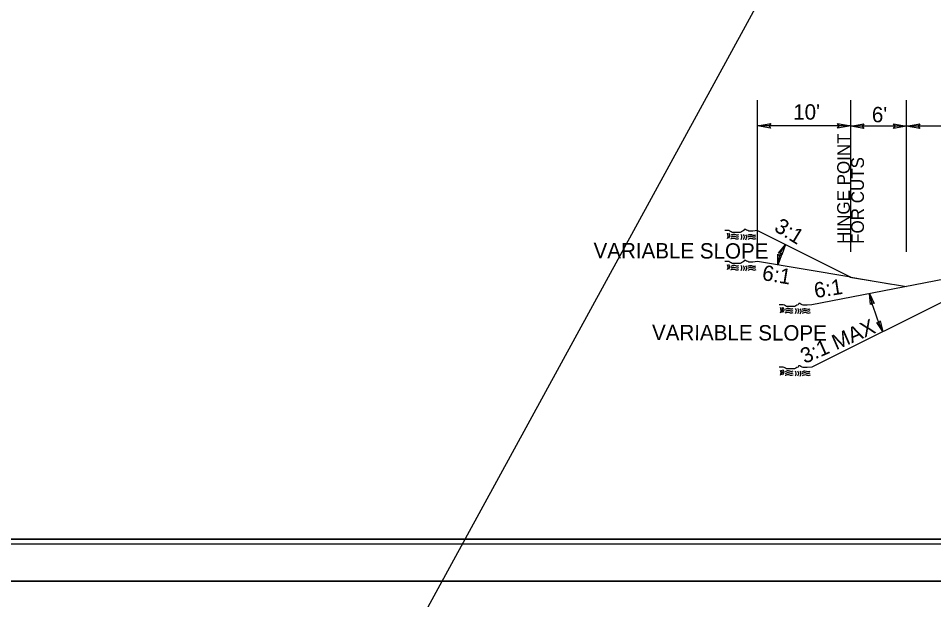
# Model space of a CAD drawing. Extents: x 2241081 to 2251104, y 658534 to 663427.
# Drawn here: x 2245690 to 2246181.2, y 660714.3 to 661026.5 of the extents above; entities that cross this region are included whole.
import ezdxf

# ---------------------------------------------------------------- set-up
doc = ezdxf.new("R2010")
doc.units = 0
for name, color, linetype in [('Old_Level_1', 7, 'Continuous'), ('Old_Level_2', 7, 'Continuous'), ('Prop Dimension', 7, 'Continuous'), ('Prop Dimension Text', 7, 'Continuous'), ('Prop PHM Text', 7, 'Continuous'), ('Sheet Cutting Line CELL', 7, 'Continuous'), ('Sheet Plan CELL', 7, 'Continuous'), ('Sheet Plot Border Inside CELL', 7, 'Continuous'), ('Sheet Plot Border Outside CELL', 7, 'Continuous'), ('Typical Hinge Slope Interstate CELL', 7, 'Continuous'), ('Typical Terminator CELL', 7, 'Continuous')]:
    doc.layers.add(name, color=color, linetype=linetype)

msp = doc.modelspace()

# ---------------------------------------------------------------- linework, layer by layer
at = {"layer": 'Old_Level_1'}
for p, q in [((2246086.68, 660912.48), (2246136.68, 660887.48)), ((2246136.68, 660887.48), (2246086.68, 660895.82)), ((2246224.69, 660893.65), (2246115.86, 660872.7)), ((2246136.68, 660887.48), (2246158.68, 660883.81))]:
    msp.add_line(p, q, dxfattribs=at)
for points in [[(2246086.68, 660912.48), (2246084.21, 660912.17), (2246083.6, 660912.17), (2246082.67, 660912.17), (2246082.06, 660912.17), (2246081.44, 660912.48), (2246080.82, 660912.79), (2246080.21, 660913.1), (2246079.59, 660913.1), (2246079.28, 660912.48), (2246078.67, 660912.17), (2246078.05, 660911.87), (2246077.43, 660911.56), (2246076.82, 660911.56), (2246076.2, 660911.56), (2246075.59, 660911.56), (2246074.97, 660911.56), (2246074.35, 660911.56), (2246073.74, 660911.56), (2246073.12, 660911.56), (2246072.5, 660911.87), (2246071.89, 660912.17), (2246071.27, 660912.48), (2246070.35, 660912.48), (2246069.73, 660912.48), (2246069.11, 660912.48)], [(2246086.68, 660895.82), (2246084.21, 660895.51), (2246083.6, 660895.51), (2246082.67, 660895.51), (2246082.06, 660895.51), (2246081.44, 660895.82), (2246080.82, 660896.13), (2246080.21, 660896.44), (2246079.59, 660896.43), (2246079.28, 660895.82), (2246078.67, 660895.51), (2246078.05, 660895.2), (2246077.43, 660894.89), (2246076.82, 660894.89), (2246076.2, 660894.89), (2246075.59, 660894.89), (2246074.97, 660894.89), (2246074.35, 660894.89), (2246073.74, 660894.89), (2246073.12, 660894.89), (2246072.5, 660895.2), (2246071.89, 660895.51), (2246071.27, 660895.82), (2246070.35, 660895.82), (2246069.73, 660895.82), (2246069.11, 660895.82)], [(2246115.86, 660872.7), (2246113.39, 660872.39), (2246112.78, 660872.39), (2246111.85, 660872.39), (2246111.23, 660872.39), (2246110.62, 660872.7), (2246110, 660873.01), (2246109.39, 660873.32), (2246108.77, 660873.32), (2246108.46, 660872.7), (2246107.84, 660872.39), (2246107.23, 660872.08), (2246106.61, 660871.78), (2246106, 660871.78), (2246105.38, 660871.78), (2246104.76, 660871.78), (2246104.15, 660871.78), (2246103.53, 660871.78), (2246102.92, 660871.78), (2246102.3, 660871.78), (2246101.68, 660872.08), (2246101.07, 660872.39), (2246100.45, 660872.7), (2246099.53, 660872.7), (2246098.91, 660872.7), (2246098.29, 660872.7)], [(2246115.82, 660839.21), (2246113.35, 660838.9), (2246112.74, 660838.9), (2246111.81, 660838.9), (2246111.19, 660838.9), (2246110.58, 660839.21), (2246109.96, 660839.52), (2246109.35, 660839.83), (2246108.73, 660839.83), (2246108.42, 660839.21), (2246107.8, 660838.9), (2246107.19, 660838.59), (2246106.57, 660838.29), (2246105.96, 660838.29), (2246105.34, 660838.29), (2246104.72, 660838.29), (2246104.11, 660838.29), (2246103.49, 660838.29), (2246102.87, 660838.29), (2246102.26, 660838.29), (2246101.64, 660838.59), (2246101.03, 660838.9), (2246100.41, 660839.21), (2246099.48, 660839.21), (2246098.87, 660839.21), (2246098.25, 660839.21)]]:
    msp.add_lwpolyline(points, dxfattribs=at)
for points in [[(2246070.37, 660911.04), (2246070.79, 660909.79), (2246070.33, 660908.14)], [(2246070.37, 660911.04), (2246070.79, 660909.79), (2246070.33, 660908.14)], [(2246071.15, 660911.12), (2246071.57, 660909.87), (2246071.12, 660908.23)], [(2246071.15, 660911.12), (2246071.57, 660909.87), (2246071.12, 660908.23)], [(2246072.35, 660908.05), (2246073.86, 660908.47), (2246075.45, 660908.07), (2246076.6, 660908.33)], [(2246072.35, 660908.05), (2246073.86, 660908.47), (2246075.45, 660908.07), (2246076.6, 660908.33)], [(2246072.47, 660909.1), (2246073.98, 660909.53), (2246075.56, 660909.12), (2246076.7, 660909.38)], [(2246072.47, 660909.1), (2246073.98, 660909.53), (2246075.56, 660909.12), (2246076.7, 660909.38)], [(2246072.48, 660910.15), (2246073.98, 660910.58), (2246075.57, 660910.18), (2246076.71, 660910.43)], [(2246072.48, 660910.15), (2246073.98, 660910.58), (2246075.57, 660910.18), (2246076.71, 660910.43)], [(2246077.74, 660910.5), (2246078.15, 660909.26), (2246077.71, 660907.62)], [(2246077.74, 660910.5), (2246078.15, 660909.26), (2246077.71, 660907.62)], [(2246079.05, 660910.4), (2246079.47, 660909.16), (2246079.02, 660907.51)], [(2246079.05, 660910.4), (2246079.47, 660909.16), (2246079.02, 660907.51)], [(2246080.26, 660910.29), (2246080.68, 660909.05), (2246080.23, 660907.41)], [(2246080.26, 660910.29), (2246080.68, 660909.05), (2246080.23, 660907.41)], [(2246081.5, 660910.01), (2246083.01, 660910.44), (2246084.6, 660910.03), (2246085.75, 660910.28)], [(2246081.5, 660910.01), (2246083.01, 660910.44), (2246084.6, 660910.03), (2246085.75, 660910.28)], [(2246081.54, 660909.06), (2246083.05, 660909.5), (2246084.64, 660909.09), (2246085.78, 660909.34)], [(2246081.54, 660909.06), (2246083.05, 660909.5), (2246084.64, 660909.09), (2246085.78, 660909.34)], [(2246081.7, 660907.97), (2246083.2, 660908.4), (2246084.79, 660907.99), (2246085.94, 660908.25)], [(2246081.7, 660907.97), (2246083.2, 660908.4), (2246084.79, 660907.99), (2246085.94, 660908.25)], [(2246070.37, 660894.37), (2246070.79, 660893.13), (2246070.33, 660891.48)], [(2246070.37, 660894.37), (2246070.79, 660893.13), (2246070.33, 660891.48)], [(2246071.15, 660894.45), (2246071.57, 660893.21), (2246071.12, 660891.56)], [(2246071.15, 660894.45), (2246071.57, 660893.21), (2246071.12, 660891.56)], [(2246072.47, 660892.44), (2246073.98, 660892.86), (2246075.56, 660892.46), (2246076.7, 660892.72)], [(2246072.47, 660892.44), (2246073.98, 660892.86), (2246075.56, 660892.46), (2246076.7, 660892.72)], [(2246072.48, 660893.48), (2246073.98, 660893.92), (2246075.57, 660893.51), (2246076.71, 660893.77)], [(2246072.48, 660893.48), (2246073.98, 660893.92), (2246075.57, 660893.51), (2246076.71, 660893.77)], [(2246077.74, 660893.84), (2246078.15, 660892.6), (2246077.71, 660890.95)], [(2246077.74, 660893.84), (2246078.15, 660892.6), (2246077.71, 660890.95)], [(2246079.05, 660893.74), (2246079.47, 660892.49), (2246079.02, 660890.84)], [(2246079.05, 660893.74), (2246079.47, 660892.49), (2246079.02, 660890.84)], [(2246080.26, 660893.63), (2246080.68, 660892.38), (2246080.23, 660890.74)], [(2246080.26, 660893.63), (2246080.68, 660892.38), (2246080.23, 660890.74)], [(2246081.5, 660893.34), (2246083.01, 660893.77), (2246084.6, 660893.36), (2246085.75, 660893.62)], [(2246081.5, 660893.34), (2246083.01, 660893.77), (2246084.6, 660893.36), (2246085.75, 660893.62)], [(2246081.54, 660892.4), (2246083.05, 660892.83), (2246084.64, 660892.42), (2246085.78, 660892.68)], [(2246081.54, 660892.4), (2246083.05, 660892.83), (2246084.64, 660892.42), (2246085.78, 660892.68)], [(2246072.35, 660891.38), (2246073.86, 660891.81), (2246075.45, 660891.41), (2246076.6, 660891.66)], [(2246072.35, 660891.38), (2246073.86, 660891.81), (2246075.45, 660891.41), (2246076.6, 660891.66)], [(2246081.7, 660891.31), (2246083.2, 660891.74), (2246084.79, 660891.33), (2246085.94, 660891.59)], [(2246081.7, 660891.31), (2246083.2, 660891.74), (2246084.79, 660891.33), (2246085.94, 660891.59)]]:
    msp.add_spline(points, degree=3, dxfattribs=at)
at = {"layer": 'Old_Level_2'}
msp.add_line((2245215.42, 659438.44), (2247357.78, 663362.06), dxfattribs=at)
for points in [[(2246098.82, 660871.11), (2246099.24, 660869.87), (2246098.78, 660868.22)], [(2246098.82, 660871.11), (2246099.24, 660869.87), (2246098.78, 660868.22)], [(2246099.55, 660871.25), (2246099.97, 660870.01), (2246099.51, 660868.36)], [(2246099.55, 660871.25), (2246099.97, 660870.01), (2246099.51, 660868.36)], [(2246100.33, 660871.34), (2246100.75, 660870.09), (2246100.3, 660868.45)], [(2246100.33, 660871.34), (2246100.75, 660870.09), (2246100.3, 660868.45)], [(2246101.53, 660868.26), (2246103.03, 660868.69), (2246104.63, 660868.29), (2246105.78, 660868.55)], [(2246101.53, 660868.26), (2246103.03, 660868.69), (2246104.63, 660868.29), (2246105.78, 660868.55)], [(2246101.65, 660869.32), (2246103.15, 660869.75), (2246104.74, 660869.34), (2246105.88, 660869.6)], [(2246101.65, 660869.32), (2246103.15, 660869.75), (2246104.74, 660869.34), (2246105.88, 660869.6)], [(2246101.66, 660870.37), (2246103.16, 660870.8), (2246104.75, 660870.39), (2246105.89, 660870.65)], [(2246101.66, 660870.37), (2246103.16, 660870.8), (2246104.75, 660870.39), (2246105.89, 660870.65)], [(2246106.91, 660870.72), (2246107.33, 660869.48), (2246106.89, 660867.83)], [(2246106.91, 660870.72), (2246107.33, 660869.48), (2246106.89, 660867.83)], [(2246108.23, 660870.62), (2246108.65, 660869.38), (2246108.2, 660867.73)], [(2246108.23, 660870.62), (2246108.65, 660869.38), (2246108.2, 660867.73)], [(2246109.44, 660870.51), (2246109.86, 660869.27), (2246109.41, 660867.62)], [(2246109.44, 660870.51), (2246109.86, 660869.27), (2246109.41, 660867.62)], [(2246110.68, 660870.23), (2246112.19, 660870.65), (2246113.77, 660870.25), (2246114.92, 660870.5)], [(2246110.68, 660870.23), (2246112.19, 660870.65), (2246113.77, 660870.25), (2246114.92, 660870.5)], [(2246110.72, 660869.28), (2246112.23, 660869.71), (2246113.81, 660869.3), (2246114.96, 660869.56)], [(2246110.72, 660869.28), (2246112.23, 660869.71), (2246113.81, 660869.3), (2246114.96, 660869.56)], [(2246110.88, 660868.19), (2246112.38, 660868.62), (2246113.97, 660868.21), (2246115.12, 660868.47)], [(2246098.78, 660837.62), (2246099.2, 660836.38), (2246098.74, 660834.73)], [(2246098.78, 660837.62), (2246099.2, 660836.38), (2246098.74, 660834.73)], [(2246099.51, 660837.76), (2246099.93, 660836.52), (2246099.47, 660834.87)], [(2246099.51, 660837.76), (2246099.93, 660836.52), (2246099.47, 660834.87)], [(2246100.29, 660837.84), (2246100.71, 660836.6), (2246100.26, 660834.96)], [(2246100.29, 660837.84), (2246100.71, 660836.6), (2246100.26, 660834.96)], [(2246101.49, 660834.77), (2246102.99, 660835.2), (2246104.59, 660834.8), (2246105.73, 660835.05)], [(2246101.49, 660834.77), (2246102.99, 660835.2), (2246104.59, 660834.8), (2246105.73, 660835.05)], [(2246101.61, 660835.83), (2246103.11, 660836.26), (2246104.7, 660835.85), (2246105.84, 660836.11)], [(2246101.61, 660835.83), (2246103.11, 660836.26), (2246104.7, 660835.85), (2246105.84, 660836.11)], [(2246101.62, 660836.88), (2246103.11, 660837.31), (2246104.71, 660836.9), (2246105.85, 660837.16)], [(2246101.62, 660836.88), (2246103.11, 660837.31), (2246104.71, 660836.9), (2246105.85, 660837.16)], [(2246106.87, 660837.23), (2246107.29, 660835.99), (2246106.84, 660834.34)], [(2246106.87, 660837.23), (2246107.29, 660835.99), (2246106.84, 660834.34)], [(2246108.19, 660837.13), (2246108.61, 660835.89), (2246108.16, 660834.24)], [(2246108.19, 660837.13), (2246108.61, 660835.89), (2246108.16, 660834.24)], [(2246109.4, 660837.02), (2246109.82, 660835.78), (2246109.37, 660834.13)], [(2246109.4, 660837.02), (2246109.82, 660835.78), (2246109.37, 660834.13)], [(2246110.64, 660836.73), (2246112.15, 660837.16), (2246113.73, 660836.76), (2246114.88, 660837.01)], [(2246110.64, 660836.73), (2246112.15, 660837.16), (2246113.73, 660836.76), (2246114.88, 660837.01)], [(2246110.68, 660835.79), (2246112.19, 660836.22), (2246113.77, 660835.81), (2246114.92, 660836.07)], [(2246110.68, 660835.79), (2246112.19, 660836.22), (2246113.77, 660835.81), (2246114.92, 660836.07)], [(2246110.84, 660834.7), (2246112.34, 660835.13), (2246113.93, 660834.72), (2246115.08, 660834.98)]]:
    msp.add_spline(points, degree=3, dxfattribs=at)
at = {"layer": 'Prop Dimension'}
for centre, radius, start, end in [((2246116.62, 660893.15), 19.12, 141.6676, 177.4305), ((2246226.2, 660895.1), 81.05, 191.6788, 206.9901)]:
    msp.add_arc(centre, radius, start, end, dxfattribs=at)
at = {"layer": 'Prop Dimension Text'}
for p, q in [((2246086.68, 660901.14), (2246086.68, 660982.61)), ((2246136.68, 660901.14), (2246136.68, 660982.61)), ((2246166.68, 660901.14), (2246166.68, 660982.61)), ((2246086.68, 660968.92), (2246086.68, 660968.92)), ((2246136.68, 660968.8), (2246086.68, 660968.8)), ((2246136.68, 660968.92), (2246136.68, 660968.92)), ((2246166.68, 660968.54), (2246136.68, 660968.54)), ((2246224.69, 660968.54), (2246166.68, 660968.54))]:
    msp.add_line(p, q, dxfattribs=at)
at = {"layer": 'Sheet Cutting Line CELL'}
for p, q in [((2245397.32, 660724.27), (2247080.82, 660724.27)), ((2247080.82, 660724.27), (2245397.32, 660724.27))]:
    msp.add_line(p, q, dxfattribs=at)
at = {"layer": 'Sheet Plan CELL'}
for points in [[(2245563.81, 660746.78), (2245563.79, 661796.76), (2246863.78, 661796.79), (2246863.79, 661646.73), (2247063.83, 661646.72), (2247063.82, 660746.78)], [(2247063.85, 661796.78), (2245563.81, 661796.78), (2245563.81, 660746.78), (2247063.82, 660746.78)]]:
    msp.add_lwpolyline(points, close=True, dxfattribs=at)
at = {"layer": 'Sheet Plot Border Inside CELL'}
msp.add_lwpolyline([(2245410.32, 660744.27), (2247076.31, 660744.28), (2247076.33, 661799.27), (2245410.33, 661799.27)], close=True, dxfattribs=at)
at = {"layer": 'Sheet Plot Border Outside CELL'}
for points in [[(2245397.32, 660724.27), (2247080.82, 660724.27), (2247080.83, 661819.27), (2245397.33, 661819.27)], [(2245397.32, 659629.27), (2247080.82, 659629.27), (2247080.82, 660724.27), (2245397.32, 660724.27)]]:
    msp.add_lwpolyline(points, close=True, dxfattribs=at)
at = {"layer": 'Typical Hinge Slope Interstate CELL'}
for p, q in [((2246224.69, 660893.65), (2246115.82, 660839.21)), ((2246136.18, 660887.56), (2246166.68, 660882.48))]:
    msp.add_line(p, q, dxfattribs=at)
at = {"layer": 'Typical Terminator CELL'}
for points in [[(2246093.71, 660967.59), (2246086.68, 660968.8), (2246093.75, 660970.05), (2246092.85, 660968.8)], [(2246129.65, 660970.01), (2246136.68, 660968.8), (2246129.61, 660967.55), (2246130.51, 660968.8)], [(2246143.71, 660967.33), (2246136.68, 660968.54), (2246143.75, 660969.79), (2246142.85, 660968.54)], [(2246159.65, 660969.75), (2246166.68, 660968.54), (2246159.61, 660967.29), (2246160.51, 660968.54)], [(2246173.71, 660967.33), (2246166.68, 660968.54), (2246173.75, 660969.79), (2246172.85, 660968.54)], [(2246097.96, 660900.44), (2246101.62, 660905.01), (2246099.71, 660899.44), (2246099.17, 660900.58)], [(2246099.51, 660899.51), (2246097.52, 660894.01), (2246097.53, 660899.9), (2246098.41, 660898.99)], [(2246147.22, 660872.86), (2246146.82, 660878.69), (2246149.19, 660873.3), (2246148.02, 660873.78)], [(2246152.57, 660864), (2246153.97, 660858.32), (2246150.7, 660863.22), (2246151.94, 660862.95)]]:
    msp.add_lwpolyline(points, close=True, dxfattribs=at)

# ---------------------------------------------------------------- texts
at = {"layer": 'Prop Dimension Text'}
for s, rotation, p in [("10'", 359.9999, (2246105.82, 660972.07)), ("6'", 359.9999, (2246148.04, 660970.67)), ('6:1', 8.8656, (2246117.69, 660876.21))]:
    msp.add_text(s, height=8.25, rotation=rotation, dxfattribs=at).set_placement(p)
at = {"layer": 'Prop PHM Text'}
for s, height, p in [('HINGE POINT', 6.8193, (2246136.25, 660905.37)), ('FOR CUTS', 6.819, (2246143.76, 660905.37))]:
    msp.add_text(s, height=height, rotation=89.9999, dxfattribs=at).set_placement(p)
at = {"layer": 'Typical Hinge Slope Interstate CELL'}
for s, rotation, p in [('3:1', 328.4414, (2246095.08, 660912.71)), ('VARIABLE SLOPE', 359.8157, (2245998.69, 660897.68)), ('6:1', 350.5376, (2246088.74, 660886.01)), ('3:1 MAX', 23.6411, (2246111.98, 660840.83)), ('VARIABLE SLOPE', 359.8157, (2246030.04, 660853.68))]:
    msp.add_text(s, height=8.25, rotation=rotation, dxfattribs=at).set_placement(p)

doc.saveas('drawing.dxf')
